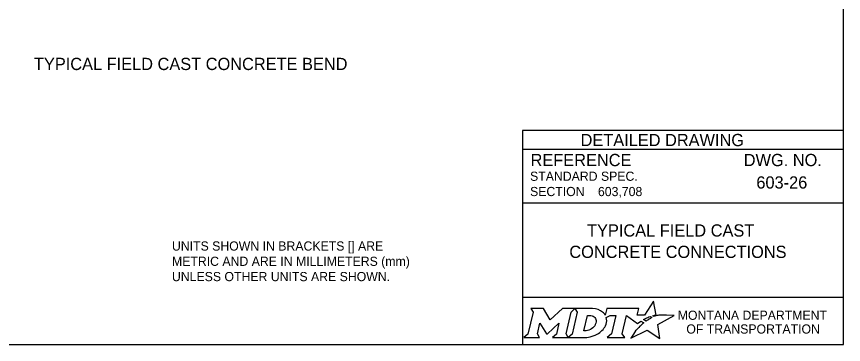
# Model space of a CAD drawing. Extents: x 49991.4 to 50021, y 49987.6 to 50011.4.
# Drawn here: x 50003.21 to 50008.61, y 50000.06 to 50002.21 of the extents above; entities that cross this region are included whole.
import ezdxf

# ---------------------------------------------------------------- set-up
doc = ezdxf.new("R2010")
doc.units = 0
doc.layers.add('Level 1', color=7, linetype='Continuous')
doc.layers.add('Level 2', color=7, linetype='Continuous')

msp = doc.modelspace()

# ---------------------------------------------------------------- linework, layer by layer
at = {"layer": 'Level 1'}
msp.add_lwpolyline([(50008.6146, 50011.2628), (50000.3356, 50011.2628), (50000.3356, 50000.0624), (50008.6146, 50000.0624)], close=True, dxfattribs=at)
at = {"layer": 'Level 2'}
for p, q in [((50008.6146, 50001.4624), (50006.5146, 50001.4624)), ((50006.5146, 50001.4624), (50006.5146, 50000.0624)), ((50008.6146, 50001.3374), (50006.5146, 50001.3374)), ((50008.2507, 50001.1223), (50008.2507, 50001.1223)), ((50007.0089, 50001.0629), (50007.0089, 50001.0629)), ((50008.6146, 50000.9874), (50006.5146, 50000.9874)), ((50007.5646, 50000.7383), (50007.5646, 50000.7383)), ((50008.6146, 50000.3693), (50006.5146, 50000.3693))]:
    msp.add_line(p, q, dxfattribs=at)
for points in [[(50007.3771, 50000.2447), (50007.3668, 50000.2503), (50007.3784, 50000.2531), (50007.39, 50000.2551), (50007.3726, 50000.3452), (50007.3131, 50000.2539), (50007.2658, 50000.2532), (50007.2761, 50000.2973), (50007.0669, 50000.2974), (50007.0568, 50000.2549), (50007.051, 50000.2632)], [(50006.5701, 50000.2974), (50006.5842, 50000.274), (50006.5507, 50000.1307), (50006.525, 50000.1082), (50006.6266, 50000.1082), (50006.6131, 50000.131), (50006.6293, 50000.2011), (50006.673, 50000.1321), (50006.6783, 50000.1321), (50006.7534, 50000.2016), (50006.737, 50000.1305), (50006.7123, 50000.1085), (50006.8139, 50000.1085), (50006.8001, 50000.1318), (50006.8333, 50000.2742)], [(50006.8333, 50000.2742), (50006.8586, 50000.2974), (50006.7762, 50000.2974), (50006.6966, 50000.2244), (50006.6521, 50000.2971), (50006.5701, 50000.2974)], [(50006.9722, 50000.2974), (50006.8586, 50000.2974), (50006.8733, 50000.2745), (50006.8394, 50000.1307), (50006.8139, 50000.1085), (50006.9245, 50000.1085)], [(50006.9962, 50000.2107), (50006.995, 50000.2026), (50006.9918, 50000.1933), (50006.9876, 50000.1851), (50006.982, 50000.1776), (50006.9755, 50000.1707), (50006.9676, 50000.1644), (50006.9593, 50000.1597), (50006.9502, 50000.1558), (50006.9411, 50000.1535), (50006.9319, 50000.1526), (50006.916, 50000.1526), (50006.9396, 50000.2526), (50006.9556, 50000.2526), (50006.9632, 50000.252), (50006.9708, 50000.2501), (50006.9774, 50000.2471), (50006.9835, 50000.2429), (50006.9883, 50000.2379), (50006.992, 50000.2319), (50006.9947, 50000.2257), (50006.9963, 50000.2183), (50006.9963, 50000.2153), (50006.9962, 50000.2107)], [(50007.0636, 50000.2383), (50007.0882, 50000.2514), (50007.1251, 50000.2514), (50007.0965, 50000.1309), (50007.069, 50000.1082), (50007.1852, 50000.1082), (50007.1682, 50000.1311), (50007.1964, 50000.2513), (50007.2677, 50000.1996), (50007.2888, 50000.2147), (50007.3085, 50000.2038)], [(50007.2527, 50000.1479), (50007.2374, 50000.1235), (50007.2327, 50000.116), (50007.2269, 50000.1074), (50007.2246, 50000.1031), (50007.3299, 50000.1562), (50007.4138, 50000.1011), (50007.4007, 50000.1938), (50007.5076, 50000.2522), (50007.4583, 50000.253), (50007.4282, 50000.2534), (50007.4074, 50000.2537), (50007.4006, 50000.2522), (50007.3957, 50000.251), (50007.3873, 50000.2487), (50007.3771, 50000.2447)], [(50007.3267, 50000.2171), (50007.3243, 50000.2154), (50007.306, 50000.225), (50007.3163, 50000.2307), (50007.3204, 50000.2329), (50007.329, 50000.2369), (50007.3347, 50000.2395), (50007.3426, 50000.2425), (50007.3499, 50000.2452), (50007.3617, 50000.2378), (50007.3577, 50000.2357), (50007.3531, 50000.2332), (50007.3489, 50000.231), (50007.3439, 50000.2281), (50007.342, 50000.227), (50007.3393, 50000.2254), (50007.3368, 50000.224), (50007.3345, 50000.2224), (50007.3319, 50000.2206), (50007.3292, 50000.2188), (50007.3267, 50000.2171)], [(50006.9702, 50000.1158), (50006.9786, 50000.1184), (50006.9916, 50000.1238), (50007.012, 50000.1348)], [(50007.2666, 50000.164), (50007.2666, 50000.164)]]:
    msp.add_lwpolyline(points, dxfattribs=at)
for centre, radius, start, end in [((50006.9953, 50000.219), 0.0709, 339.5329, 15.8582), ((50006.9513, 50000.2363), 0.1183, 300.9103, 339.1383)]:
    msp.add_arc(centre, radius, start, end, dxfattribs=at)
for centre, major_axis, ratio, start_param, end_param in [((50006.9701, 50000.25), (0.0834, -0.0037), 0.568097, 0.61298, 1.570796), ((50007.0257, 50000.2573), (0.0361, -0.0295), 0.469099, 1.225588, 1.570796), ((50007.2764, 50000.1742), (-0.0098, -0.0102), 0.016458, 3.141593, 6.279097), ((50007.2974, 50000.1941), (-0.0112, -0.0097), 0.021651, 3.157348, 6.283185), ((50007.2597, 50000.1559), (-0.00694, -0.00806), 0.008222, 0, 3.137361), ((50006.9248, 50000.2568), (0, 0.1484), 0.987302, 3.139398, 3.456847)]:
    msp.add_ellipse(centre, major_axis=major_axis, ratio=ratio, start_param=start_param, end_param=end_param, dxfattribs=at)

# ---------------------------------------------------------------- texts
for s, height, p in [('TYPICAL FIELD CAST CONCRETE BEND', 0.08, (50003.3201, 50001.8577)), ('DETAILED DRAWING', 0.0799, (50006.8956, 50001.3599)), ('REFERENCE', 0.08, (50006.5682, 50001.229)), ('DWG. NO.', 0.08, (50007.9624, 50001.229)), ('STANDARD SPEC.', 0.06, (50006.5649, 50001.133)), ('603-26', 0.08, (50008.0449, 50001.0823)), ('SECTION', 0.06, (50006.5649, 50001.033)), ('603,708', 0.06, (50007.0089, 50001.0329)), ('TYPICAL FIELD CAST', 0.08, (50006.9376, 50000.7683)), ('UNITS SHOWN IN BRACKETS [] ARE ', 0.06, (50004.2229, 50000.6766)), ('CONCRETE CONNECTIONS', 0.08, (50006.8218, 50000.6283)), ('METRIC AND ARE IN MILLIMETERS (mm) ', 0.06, (50004.2229, 50000.5766)), ('UNLESS OTHER UNITS ARE SHOWN.', 0.06, (50004.2229, 50000.4766)), ('MONTANA DEPARTMENT', 0.06, (50007.5308, 50000.2236)), ('OF TRANSPORTATION', 0.06, (50007.587, 50000.1336))]:
    msp.add_text(s, height=height, dxfattribs=at).set_placement(p)

doc.saveas('drawing.dxf')
